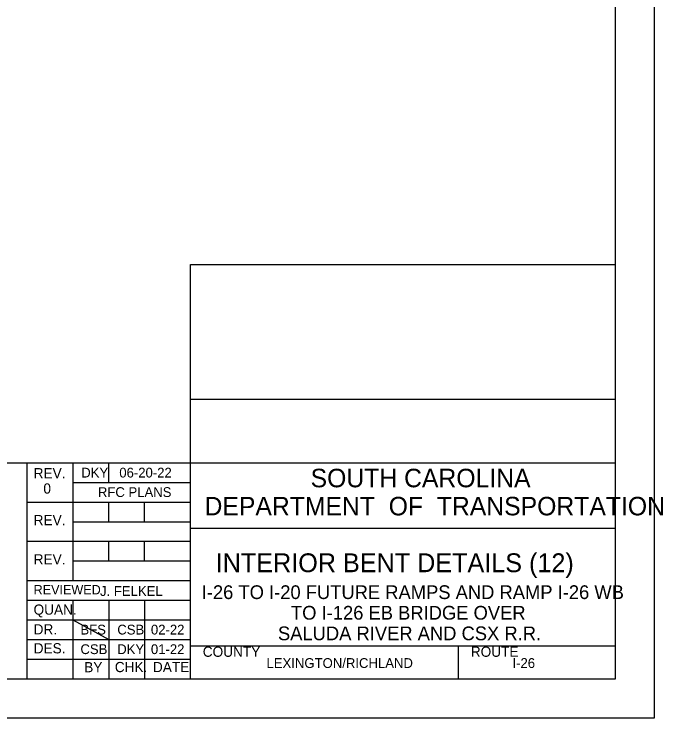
# Model space of a CAD drawing. Extents: x -144.4 to -96.3, y -117.1 to -87.8.
# Drawn here: x -107.33 to -96.33, y -117.06 to -105.14 of the extents above; entities that cross this region are included whole.
import ezdxf

# ---------------------------------------------------------------- set-up
doc = ezdxf.new("R2010")
doc.units = 0
for name, color, linetype in [('BR_BORDER LINES', 7, 'Continuous'), ('BR_TEXT', 7, 'Continuous'), ('Level 31', 7, 'Continuous')]:
    doc.layers.add(name, color=color, linetype=linetype)

msp = doc.modelspace()

# ---------------------------------------------------------------- linework, layer by layer
at = {"layer": 'BR_BORDER LINES'}
for p, q in [((-97.136, -116.398), (-97.136, -88.468)), ((-104.341, -116.398), (-104.341, -109.38)), ((-104.341, -109.38), (-97.136, -109.38)), ((-104.34, -111.66), (-97.136, -111.66)), ((-114.247, -112.74), (-107.112, -112.74)), ((-107.112, -116.398), (-107.112, -112.74)), ((-107.112, -112.74), (-97.136, -112.74)), ((-106.336, -112.74), (-106.336, -114.735)), ((-105.726, -113.072), (-105.726, -112.74)), ((-106.336, -113.072), (-104.341, -113.072)), ((-107.112, -113.405), (-104.341, -113.405)), ((-105.726, -113.737), (-105.726, -113.405)), ((-105.117, -113.737), (-105.117, -113.405)), ((-106.336, -113.737), (-104.341, -113.737)), ((-104.341, -113.848), (-104.341, -113.848)), ((-104.341, -113.848), (-97.136, -113.848)), ((-107.112, -114.07), (-104.341, -114.07)), ((-105.726, -114.403), (-105.726, -114.07)), ((-105.117, -114.403), (-105.117, -114.07)), ((-106.336, -114.403), (-104.341, -114.403)), ((-107.112, -114.735), (-104.341, -114.735)), ((-107.112, -115.068), (-104.341, -115.068)), ((-106.336, -115.068), (-106.336, -116.398)), ((-105.726, -115.068), (-105.726, -116.398)), ((-105.117, -115.068), (-105.117, -116.398)), ((-107.112, -115.4), (-104.341, -115.4)), ((-107.112, -115.733), (-104.341, -115.733)), ((-104.341, -115.843), (-97.136, -115.843)), ((-104.211, -115.843), (-97.136, -115.843)), ((-99.796, -116.398), (-99.796, -115.843)), ((-107.112, -116.065), (-104.341, -116.065)), ((-141.912, -116.398), (-97.136, -116.398))]:
    msp.add_line(p, q, dxfattribs=at)
at = {"layer": 'Level 31'}
for p, q in [((-100.738, -114.434), (-100.738, -114.434)), ((-106.336, -115.4), (-105.726, -115.733))]:
    msp.add_line(p, q, dxfattribs=at)
msp.add_lwpolyline([(-144.35, -117.062), (-96.47, -117.062), (-96.47, -87.803), (-144.35, -87.803)], close=True, dxfattribs=at)

# ---------------------------------------------------------------- texts
at = {"layer": 'BR_TEXT'}
for s, height, p in [('REV.', 0.1729, (-106.999, -113.002)), ('DKY', 0.1662, (-106.192, -112.989)), ('06-20-22', 0.1662, (-105.547, -112.989)), ('SOUTH CAROLINA', 0.31371, (-102.303, -113.154)), ('0', 0.173, (-106.834, -113.261)), ('RFC PLANS', 0.1662, (-105.91, -113.319)), ('DEPARTMENT  OF  TRANSPORTATION', 0.31371, (-104.102, -113.63)), ('REV.', 0.1729, (-106.999, -113.797)), ('INTERIOR BENT DETAILS (12)', 0.3192, (-103.912, -114.593)), ('REV.', 0.1729, (-106.999, -114.462)), ('REVIEWED', 0.1596, (-107, -114.97)), ('J. FELKEL', 0.1662, (-105.874, -114.995)), ('I-26 TO I-20 FUTURE RAMPS AND RAMP I-26 WB', 0.23275, (-104.15, -115.048)), ('QUAN.', 0.1729, (-107.001, -115.313)), ('TO I-126 EB BRIDGE OVER', 0.23275, (-102.636, -115.397)), ('DR.', 0.1729, (-107, -115.648)), ('BFS', 0.1662, (-106.206, -115.649)), ('CSB', 0.1662, (-105.581, -115.649)), ('02-22', 0.1662, (-105.011, -115.649)), ('SALUDA RIVER AND CSX R.R.', 0.23275, (-102.857, -115.746)), ('DES.', 0.1729, (-106.999, -115.969)), ('CSB', 0.1662, (-106.206, -115.981)), ('01-22', 0.1662, (-105.011, -115.981)), ('DKY', 0.1662, (-105.582, -115.981)), ('COUNTY', 0.1729, (-104.132, -116.027)), ('ROUTE', 0.1729, (-99.587, -116.027)), ('LEXINGTON/RICHLAND', 0.16624, (-103.051, -116.216)), ('I-26', 0.1662, (-98.88, -116.216)), ('BY', 0.1729, (-106.142, -116.289)), ('CHK.', 0.1729, (-105.623, -116.287)), ('DATE', 0.1729, (-104.977, -116.287))]:
    msp.add_text(s, height=height, dxfattribs=at).set_placement(p)

doc.saveas('drawing.dxf')
